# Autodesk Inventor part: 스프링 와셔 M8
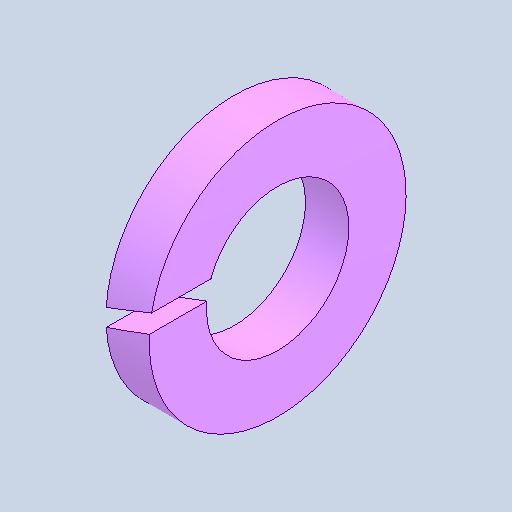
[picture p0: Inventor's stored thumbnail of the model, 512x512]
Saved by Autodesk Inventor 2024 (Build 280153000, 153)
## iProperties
Created: 2024-11
Part Number: 스프링 와셔 M8
Material: 강철, 연강
Description: 스프링 잠금 와셔
Document SubType Name: Modeling
Designer: user
Density: 7.85 g/cm^3
Appearance: 기본값
Author: jhkim
Sending System: Autodesk Inventor 2025
Preprocessor: ST-DEVELOPER v20
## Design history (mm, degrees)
node "스프링 와셔 M81"
node "솔리드1"
body "Solid1"
